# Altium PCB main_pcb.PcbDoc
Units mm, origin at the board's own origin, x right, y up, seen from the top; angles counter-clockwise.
Board outline 70 x 30 mm, 2 copper layers (Top Layer, Bottom Layer); 32 components, 25 nets, 92 pads, 0 vias.
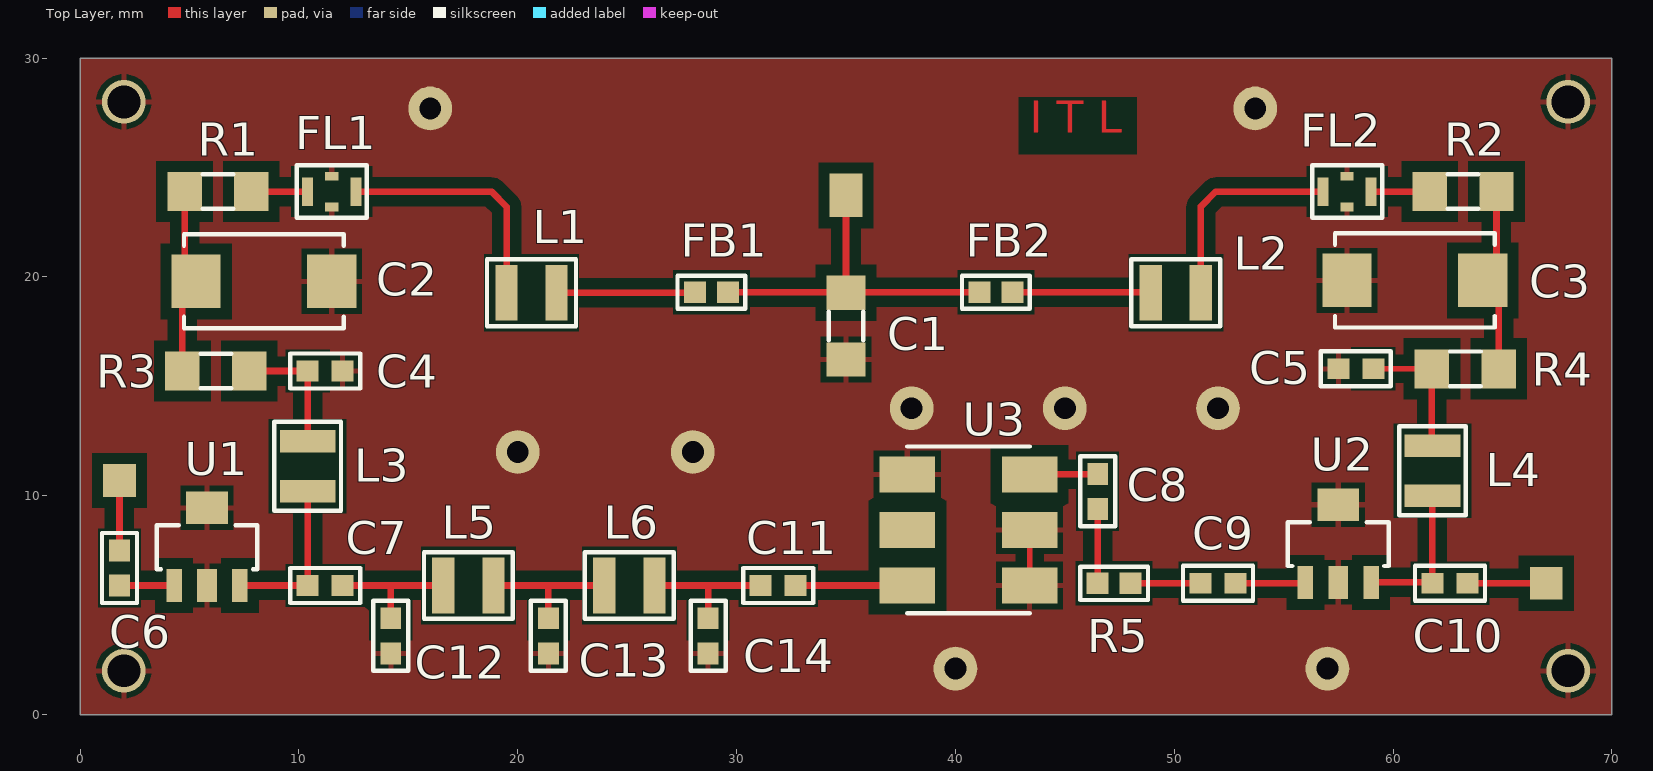
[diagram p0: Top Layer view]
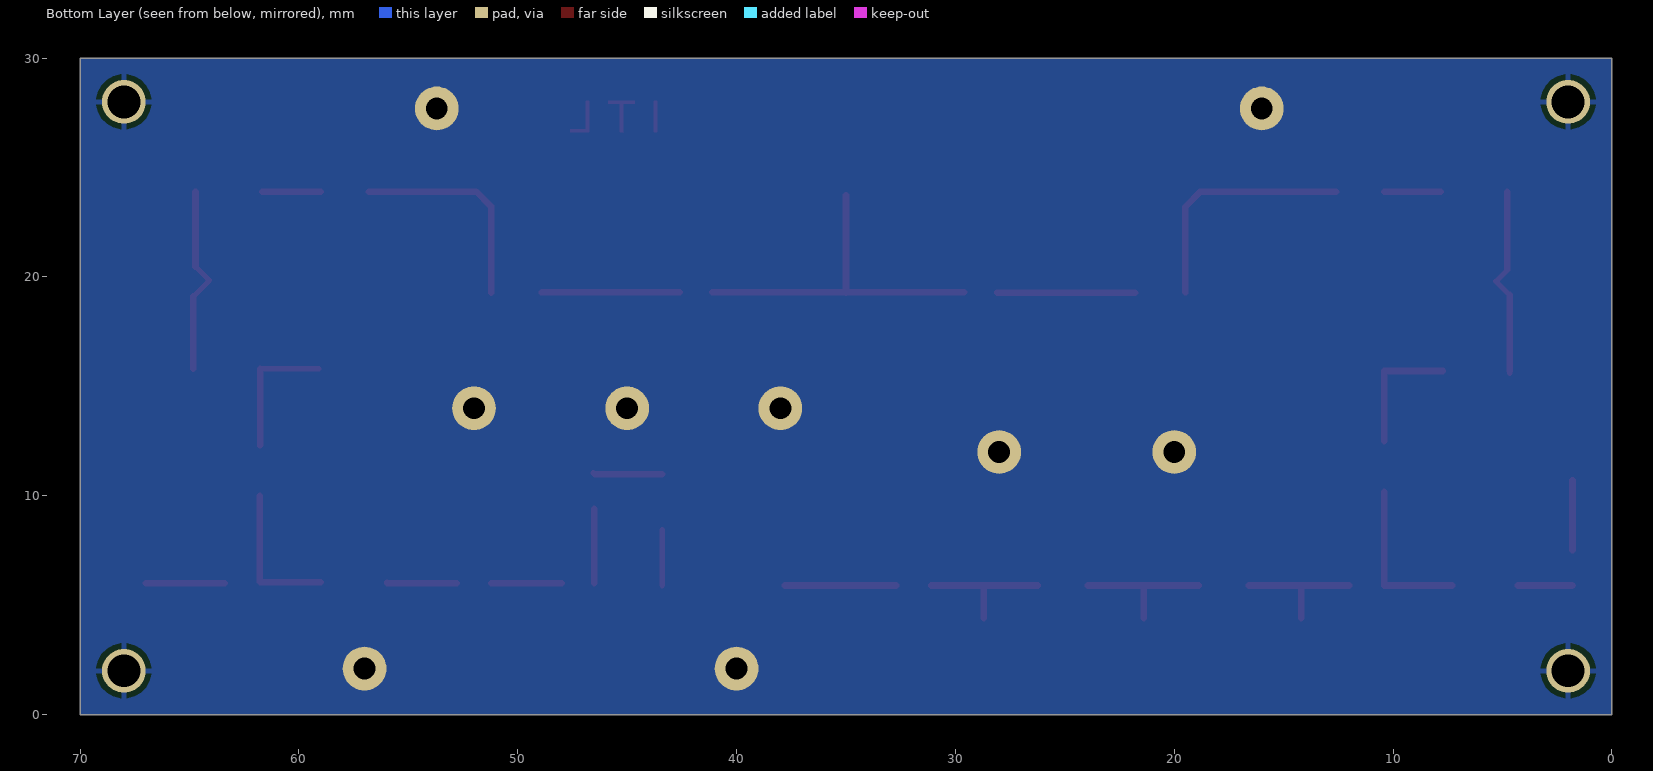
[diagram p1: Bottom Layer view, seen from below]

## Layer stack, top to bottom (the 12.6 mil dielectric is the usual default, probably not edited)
Top Solder: solder mask 0.0102, Solder Resist, Dk 3.5
Top Layer: signal copper 0.0356
Dielectric 1: dielectric 0.32, FR-4, Dk 4.8
Bottom Layer: signal copper 0.0356
Bottom Solder: solder mask 0.0102, Solder Resist, Dk 3.5

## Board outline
0,0 70,0 70,30 0,30

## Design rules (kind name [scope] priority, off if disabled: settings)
Clearance [All] p1: gap=0.5 ignorepadtopadclearanceinfootprint=FALSE
PolygonConnect [All] p1: connectstyle=Relief reliefconductorwidth=0.254 reliefentries=4 polygonreliefangle="90 Angle" airgapwidth=0.254
RoomDefinition main_sch [InComponentClass('main_sch')] p1: confinementstyle=ConfineIn formatcopy=TRUE lockcomponents=FALSE outline 153.797,0.127 166.5,0.127 166.5,13.6 153.797,13.6
RoutingVias [All] p1: holewidth=0.711 width=1.27 viastyle="Through Hole" minholewidth=0.711 minwidth=1.27 maxholewidth=0.711 maxwidth=1.27
SolderMaskExpansion [All] p1: expansion=0.102 istentingtop=FALSE
Width [All] p1: maxlimit=0.254 minlimit=0.254 preferedwidth=0.254
30 further rules are at their usual default settings.

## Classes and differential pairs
component class main_sch: C1 C4 C5 C6 C8 C10 C11 FB1 FB2 FL1 FL2 L1 L2 L3 L4 L5 L6 R3 U1 U2 U3

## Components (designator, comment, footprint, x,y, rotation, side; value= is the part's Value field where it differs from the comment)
C1 "10u" CAPC3216X06N 35,17.752 r90 top
C2 "10u" CAPM7343X15N 8.4,19.8 r0 top
C3 "10u" CAPM7343X15N 60.995,19.84 r180 top
C4 "280p" C0603 11.2,15.7 r0 top
C5 "280p" C0603 58.3,15.8 r180 top
C6 "100n" C0603 1.8,6.7 r270 top
C7 "100n" C0603 11.2,5.9 r0 top
C8 "50n" C0603 46.5,10.2 r90 top
C9 "50n" C0603 52,6 r0 top
C10 "50n" C0603 62.6,6 r0 top
C11 "100n" C0603 31.9,5.9 r180 top
C12 "380p" C0603 14.2,3.6 r90 top
C13 "280p" C0603 21.4,3.6 r90 top
C14 "280p" C0603 28.7,3.6 r90 top
FB1 "0.5" R0603 28.8,19.3 r0 top
FB2 "0.5" R0603 41.8,19.3 r0 top
FL1 "26n" C0805-X2Y 11.5,23.9 r180 top
FL2 "26n" C0805-X2Y 57.9,23.9 r180 top
L1 "4u" L1008 20.628,19.277 r0 top
L2 "4u" L1008 50.073,19.277 r0 top
L3 "3.5u" L1008 10.4,11.345 r90 top
L4 "3.5u" L1008 61.8,11.145 r90 top
L5 "30n" L1008 17.745,5.9 r0 top
L6 "30n" L1008 25.1,5.9 r0 top
R1 "23.7" RESC3216X06N 6.3,23.9 r0 top
R2 "23.7" RESC3216X06N 63.2,23.9 r180 top
R3 "19.6" RESC3216X06N 6.2,15.7 r180 top
R4 "19.6" RESC3216X06N 63.3,15.8 r0 top
R5 "0" R0603 47.2,6 r0 top
U1 "GALI-6+" DF782 5.8,8.05 r90 top
U2 "GALI-6+" DF782 57.495,8.19 r90 top
U3 "AMK-2-13+" CD542 40.595,8.44 r0 top

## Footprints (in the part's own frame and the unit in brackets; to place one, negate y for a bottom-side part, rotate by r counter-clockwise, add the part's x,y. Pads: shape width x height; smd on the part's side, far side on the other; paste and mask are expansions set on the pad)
C0603 [mm]
  rect 1x0.95 smd: 1(-0.8,0) 2(0.8,0)
  silkscreen extent -1.6,-0.8 1.6,0.8
C0805-X2Y [mm]
  rect 0.5x1.3 smd: 1(-1.1,0) 2(1.1,0)
  rect 0.6x0.4 smd: 3(0,0.7) 4(0,-0.7)
  silkscreen extent -1.6,-1.2 1.6,1.2, body extent -1,-0.6 1,0.6, height 0.96
CAPC3216X06N [mm] "Chip Capacitor, 2-Leads, Body 3,20x1,60mm, IPC Medium Density"
  rect 1.57x1.78 smd: 1(-1.525,0) 2(1.525,0)
  silkscreen extent -0.65,-0.79 0.65,0.79, body extent -1.6,-0.8 1.6,0.8, height 0.6
CAPM7343X15N [mm] "Molded Capacitor, 2-Leads, Body 7,30x4,30mm, IPC Medium Density"
  rect 2.25x2.45 smd: 1(-3.1,0) 2(3.1,0)
  silkscreen extent -3.65,-2.15 3.65,2.15, body extent -3.87,-2.15 3.87,2.15, height 1.5
CD542 [mm]
  rect 2.54x1.65 smd: 1(-2.795,2.54) 2(-2.795,0) 3(-2.795,-2.54) 4(2.795,-2.54) 5(2.795,0) 6(2.795,2.54)
  silkscreen extent -2.79,-3.81 2.79,3.81
DF782 [mm]
  rect 1.5x0.71 smd: 1(-2.15,1.5) 3(-2.15,-1.5)
  rect 1.5x0.91 smd: 2(-2.15,0)
  rect 1.5x1.9 smd: 4(1.4,0)
  silkscreen extent -1.4,-2.3 0.6,2.3
L1008 [mm]
  rect 1.02x2.54 smd: 1(-1.145,0) 2(1.145,0)
  silkscreen extent -2.03,-1.52 2.03,1.52
R0603 [mm]
  rect 1x1 smd: 1(-0.7,0) 2(0.8,0)
  silkscreen extent -1.5,-0.76 1.6,0.76, body extent -0.89,-0.4 0.71,0.4, height 0.85
RESC3216X06N [mm] "Chip Resistor, 2-Leads, Body 3,20x1,60mm, IPC Medium Density"
  rect 1.57x1.78 smd: 1(-1.525,0) 2(1.525,0)
  silkscreen extent -0.7,-0.79 0.7,0.79, body extent -1.6,-0.8 1.6,0.8, height 0.6

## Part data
C1: library part C1206, "smd capacitor, 1206"
C2 C3: library part C_tantalum_2917, "Tantalum capacitor, size 2917"
C4 C5 C6 C7 C8 C9 C10 C11 C12 C13 C14: library part C0603, "CAP CER 0.1UF 50V X7R 0603"
FB1 FB2: library part FB0603, "Ferite beads 0603"
FL1 FL2: library part C0805-X2Y, "CAP 0.1UF 50V X2Y 0805"
L1 L2 L3 L4 L5 L6: library part 1008CT-, "CHIP INDUCTOR SMD 1008"
R1 R2 R3 R4: library part R1206, "smd resistor, 1206"
R5: library part R0603, "RES SMD OHM 1% 0603"
U1 U2: "MMIC 50Ω DC to 4 GHz"
U3: "Mini-Circuits Frequency Multiplier X2 50Ω Output 20 to 1000 MHz"

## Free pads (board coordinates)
  round 2 hole 1.5: 1(2,2) 1(2,28) 1(68,2) 1(68,28)
  round 2 hole 1: 2(16,27.7) 2(20,12) 2(28,12) 2(38,14) 2(40,2.1) 2(45,14) 2(52,14) 2(53.7,27.7) 2(57,2.1)
  rect 1.5x1.5 smd: 3(1.8,10.7) 3(67,6)
  rect 1.5x2 smd: 3(35,23.727)

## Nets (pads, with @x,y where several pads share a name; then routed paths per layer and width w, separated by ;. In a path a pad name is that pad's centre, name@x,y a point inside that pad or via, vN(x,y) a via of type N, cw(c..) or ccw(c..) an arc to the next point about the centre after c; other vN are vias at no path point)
"+8 V": C1.2 FB1.2 FB2.1 pad.3@35,23.727 | length 16
  Top Layer w0.254: C1.2@34.977,19.3 C1.2 C1.2@35.023,19.3
  Top Layer w0.3: FB1.2 C1.2@34.977,19.3 ; C1.2 pad.3@35,23.727 ; C1.2@35.023,19.3 FB2.1
GND: C1.1 C2.2 C3.2 C4.2 C5.2 C12.1 C13.1 C14.1 FL1.3 FL1.4 FL2.3 FL2.4 pad.1 pad.2 U1.2 U1.4 U2.2 U2.4 U3.1 U3.4 U3.5 | length 2.5
  Top Layer w0.254: U3.4 U3.5
in: C6.1 pad.3@1.8,10.7 | length 3.2
  Top Layer w0.3: C6.1 pad.3@1.8,10.7
NetC2_1: C2.1 R1.1 R3.2 | length 8.8
  Top Layer w0.254: R3.2@4.675,15.595 R3.2 ; C2.1@4.675,19.175 C2.1 C2.1@4.775,20.325
  Top Layer w0.3: R3.2 C2.1@4.675,19.175 ; C2.1@4.775,20.325 R1.1
NetC3_1: C3.1 R2.1 R4.2 | length 8.7
  Top Layer w0.254: C3.1@64.725,20.47 C3.1 C3.1@64.825,19.11
  Top Layer w0.3: C3.1@64.725,20.47 R2.1 ; R4.2 C3.1@64.825,19.11
NetC4_1: C4.1 L3.2 R3.1 | length 5.9
  Top Layer w0.254: R3.1@7.7,15.725 R3.1
  Top Layer w0.3: R3.1 C4.1 L3.2
NetC5_1: C5.1 L4.2 R4.1 | length 6.2
  Top Layer w0.254: C5.1 R4.1 ; L4.2@61.775,12.315 L4.2
  Top Layer w0.3: L4.2@61.775,12.315 R4.1
NetC6_2: C6.2 U1.1 | length 2.5
  Top Layer w0.3: C6.2 U1.1
NetC7_1: C7.1 L3.1 U1.3 | length 7.4
  Top Layer w0.254: L3.1@10.4,10.18 10.39,10.19 L3.1
  Top Layer w0.3: U1.3 C7.1 L3.1@10.4,10.18
NetC7_2: C7.2 C12.2 L5.1 | length 6.1
  Top Layer w0.254: 14.2,5.8 14.3,5.9
  Top Layer w0.3: C7.2 14.3,5.9 L5.1 ; C12.2 14.2,5.8
NetC8_1: C8.1 R5.1 | length 3.4
  Top Layer w0.3: R5.1 C8.1
NetC8_2: C8.2 U3.6 | length 3.2
  Top Layer w0.254: C8.2@46.48,10.98 C8.2 C8.2@46.54,11.04
  Top Layer w0.3: U3.6 C8.2@46.48,10.98
NetC9_1: C9.1 R5.2 | length 3.2
  Top Layer w0.3: R5.2 C9.1
NetC9_2: C9.2 U2.1 | length 3.2
  Top Layer w0.254: U2.1@55.955,6 U2.1
  Top Layer w0.3: C9.2 U2.1@55.955,6
NetC10_1: C10.1 L4.1 U2.3 | length 6.7
  Top Layer w0.254: C10.1@61.76,6.04 C10.1@61.8,6.08
  Top Layer w0.3: U2.3 C10.1@61.76,6.04 ; C10.1@61.8,6.08 L4.1
NetC11_1: C11.1 U3.3 | length 5.1
  Top Layer w0.3: C11.1 U3.3
NetC11_2: C11.2 C14.2 L6.2 | length 6.4
  Top Layer w0.3: L6.2 28.7,5.9 ; C14.2 28.7,5.9 ; C11.2 28.7,5.9
NetC13_2: C13.2 L5.2 L6.1 | length 6.6
  Top Layer w0.3: L5.2 21.4,5.9 ; C13.2 21.4,5.9 ; L6.1 21.4,5.9
NetFB1_1: FB1.1 L1.2 | length 6.3
  Top Layer w0.254: FB1.1@28.077,19.277 FB1.1
  Top Layer w0.3: L1.2 FB1.1@28.077,19.277
NetFB2_2: FB2.2 L2.1 | length 6.3
  Top Layer w0.254: L2.1@48.905,19.3 L2.1
  Top Layer w0.3: FB2.2 L2.1@48.905,19.3
NetFL1_1: FL1.1 L1.1 | length 11.1
  Top Layer w0.254: L1.1 L1.1@19.5,19.294
  Top Layer w0.3: FL1.1 18.8,23.9 19.5,23.2 L1.1@19.5,19.294
NetFL1_2: FL1.2 R1.2 | length 2.6
  Top Layer w0.3: R1.2 FL1.2
NetFL2_1: FL2.1 R2.2 | length 2.7
  Top Layer w0.3: FL2.1 R2.2
NetFL2_2: FL2.2 L2.2 | length 9.8
  Top Layer w0.3: L2.2 51.218,23.218 51.9,23.9 FL2.2
out: C10.2 pad.3@67,6 | length 3.6
  Top Layer w0.3: C10.2 pad.3@67,6
pads on no net: U3.2
copper on no net: | length 0
  Top Layer w0.254: 19.483,19.277 19.5,19.294

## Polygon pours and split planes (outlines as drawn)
GND on Bottom Layer "GND_L02_P001" (solid, pour order 1): 0,0 0,30 70,30 70,0
GND on Top Layer "GND_L01_P000" (solid, pour order 0): 0,0 0,30 70,30 70,0

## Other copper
Top Layer:
  text "I T L" at 43.4,26.1 h2.5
